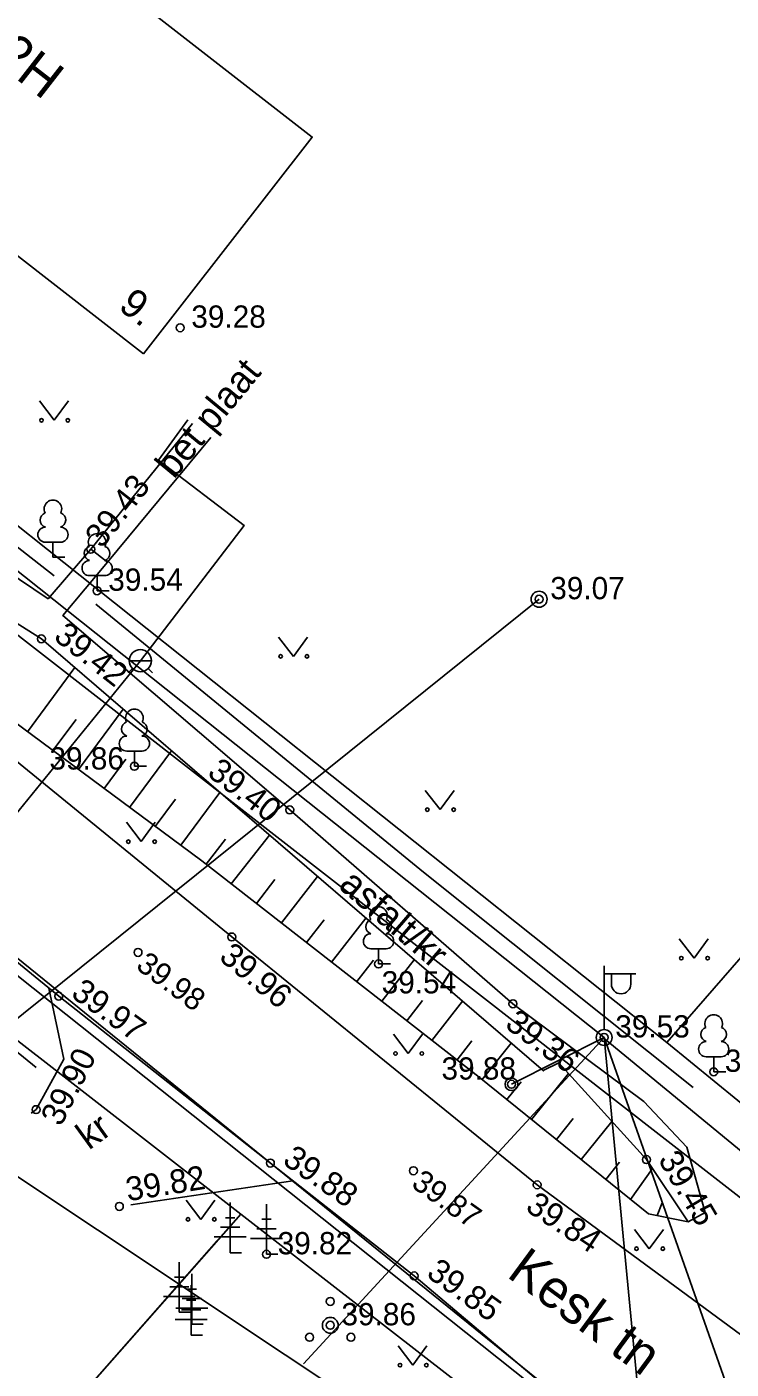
# Model space of a CAD drawing. Extents: x 641898 to 642452, y 6471715 to 6472255.
# Drawn here: x 642337.37 to 642359.52, y 6471802.88 to 6471845.1 of the extents above; entities that cross this region are included whole.
import ezdxf

# ---------------------------------------------------------------- set-up
doc = ezdxf.new("R2010")
doc.units = 0
for name, color, linetype in [('HALJASTUS', 7, 'Continuous'), ('HOONE', 7, 'Continuous'), ('KORGUS-EH2000', 7, 'Continuous'), ('KTRASS', 7, 'Continuous'), ('MPOHULIIN', 7, 'Continuous'), ('PIIR', 7, 'Continuous'), ('POST', 7, 'Continuous'), ('PUU', 7, 'Continuous'), ('RELJEEF', 7, 'Continuous'), ('SIOHULIIN', 7, 'Continuous'), ('TEE', 7, 'Continuous'), ('VKAEV', 7, 'Continuous'), ('VTRASS', 7, 'Continuous')]:
    doc.layers.add(name, color=color, linetype=linetype)

msp = doc.modelspace()

# ---------------------------------------------------------------- linework, layer by layer
at = {"layer": 'HALJASTUS'}
for p, q in [((642337.772, 6471833.33), (642338.235, 6471832.723)), ((642338.235, 6471832.723), (642338.681, 6471833.33)), ((642345.289, 6471825.904), (642345.752, 6471825.297)), ((642345.752, 6471825.297), (642346.198, 6471825.904)), ((642349.899, 6471821.085), (642350.363, 6471820.478)), ((642350.363, 6471820.478), (642350.808, 6471821.085)), ((642340.503, 6471820.079), (642340.966, 6471819.472)), ((642340.966, 6471819.472), (642341.412, 6471820.079)), ((642357.886, 6471816.413), (642358.35, 6471815.807)), ((642358.35, 6471815.807), (642358.795, 6471816.413)), ((642348.901, 6471813.416), (642349.364, 6471812.81)), ((642349.364, 6471812.81), (642349.81, 6471813.416)), ((642342.378, 6471808.199), (642342.842, 6471807.592)), ((642342.842, 6471807.592), (642343.287, 6471808.199)), ((642356.477, 6471807.276), (642356.94, 6471806.669)), ((642356.94, 6471806.669), (642357.386, 6471807.276)), ((642349.044, 6471803.615), (642349.507, 6471803.009)), ((642349.507, 6471803.009), (642349.953, 6471803.615))]:
    msp.add_line(p, q, dxfattribs=at)
for points in [[(642338.237, 6471827.832), (642333.487, 6471831.54), (642329.756, 6471834.57), (642322.893, 6471840.028), (642321.288, 6471841.543), (642315.856, 6471845.602)], [(642315.02, 6471830.765), (642322.645, 6471824.366), (642330.843, 6471817.92), (642337.665, 6471812.365)], [(642358.324, 6471811.739), (642349.848, 6471818.515), (642339.538, 6471826.94)]]:
    msp.add_lwpolyline(points, dxfattribs=at)
for centre in [(642337.834, 6471832.723), (642338.663, 6471832.723), (642345.351, 6471825.297), (642346.18, 6471825.297), (642349.962, 6471820.478), (642350.79, 6471820.478), (642340.565, 6471819.472), (642341.394, 6471819.472), (642357.949, 6471815.807), (642358.777, 6471815.807), (642348.963, 6471812.81), (642349.792, 6471812.81), (642342.441, 6471807.592), (642343.269, 6471807.592), (642356.539, 6471806.669), (642357.368, 6471806.669), (642349.106, 6471803.009), (642349.935, 6471803.009)]:
    msp.add_circle(centre, 0.055, dxfattribs=at)
at = {"layer": 'HOONE'}
msp.add_lwpolyline([(642341.045, 6471834.813), (642327.491, 6471845.358), (642330.674, 6471849.455), (642329.02, 6471850.529), (642329.906, 6471851.774), (642331.522, 6471850.559), (642332.775, 6471852.187), (642346.347, 6471841.629), (642341.045, 6471834.813)], dxfattribs=at)
at = {"layer": 'KORGUS-EH2000'}
for centre in [(642342.194, 6471835.634), (642339.384, 6471828.665), (642339.583, 6471827.362), (642353.478, 6471827.095), (642337.832, 6471825.85), (642340.755, 6471821.843), (642345.639, 6471820.471), (642343.817, 6471816.473), (642340.869, 6471815.987), (642348.43, 6471815.627), (642338.375, 6471814.612), (642352.656, 6471814.372), (642355.522, 6471813.313), (642358.966, 6471812.233), (642352.61, 6471811.841), (642337.666, 6471811.043), (642345.029, 6471809.364), (642356.853, 6471809.472), (642349.528, 6471809.121), (642353.417, 6471808.678), (642340.282, 6471807.999), (642344.908, 6471806.494), (642349.55, 6471805.814), (642346.914, 6471804.261)]:
    msp.add_circle(centre, 0.125, dxfattribs=at)
at = {"layer": 'KTRASS'}
msp.add_lwpolyline([(642365.181, 6471793.039), (642325.676, 6471825.028)], dxfattribs=at)
at = {"layer": 'MPOHULIIN'}
for points in [[(642355.522, 6471813.313), (642331.534, 6471832.393), (642302.222, 6471855.921), (642271.629, 6471880.301), (642234.793, 6471909.555), (642198.436, 6471939.015), (642169.975, 6471961.956), (642133.076, 6471995.171), (642102.99, 6472021.089), (642074.552, 6472045.947), (642044.597, 6472041.824), (642019.939, 6472060.923), (641980.015, 6472091.706), (641945.513, 6472065.466), (641932.178, 6472056.628)], [(642346.067, 6471803.048), (642355.522, 6471813.313)], [(642373.322, 6471767.398), (642363.199, 6471791.543), (642355.522, 6471813.313)], [(642357.511, 6471792.498), (642355.522, 6471813.313)], [(642373.797, 6471741.516), (642403.517, 6471768.837), (642381.866, 6471791.606), (642355.525, 6471813.278)]]:
    msp.add_lwpolyline(points, dxfattribs=at)
at = {"layer": 'PIIR'}
for p, q in [((642294.31, 6471859.27), (642377.02, 6471794.87)), ((642357.49, 6471813.15), (642303.46, 6471856.17)), ((642344.1, 6471807.76), (642288.16, 6471851.19)), ((642374.64, 6471832.89), (642357.49, 6471813.15)), ((642374.36, 6471799.41), (642357.49, 6471813.15)), ((642344.1, 6471807.76), (642326.114, 6471787.348)), ((642343.35, 6471806.91), (642344.1, 6471807.76)), ((642370.2, 6471787.49), (642344.1, 6471807.76)), ((642326.114, 6471787.348), (642343.35, 6471806.91))]:
    msp.add_line(p, q, dxfattribs=at)
at = {"layer": 'POST'}
for p, q in [((642355.522, 6471813.563), (642355.522, 6471815.563)), ((642355.522, 6471815.313), (642356.522, 6471815.313)), ((642355.749, 6471814.992), (642355.749, 6471815.313)), ((642356.361, 6471814.992), (642356.361, 6471815.313)), ((642352.61, 6471811.841), (642355.522, 6471813.313))]:
    msp.add_line(p, q, dxfattribs=at)
for centre, radius in [((642353.478, 6471827.095), 0.25), ((642355.522, 6471813.313), 0.25), ((642352.61, 6471811.841), 0.2)]:
    msp.add_circle(centre, radius, dxfattribs=at)
msp.add_arc((642356.055, 6471814.992), 0.306, 180, 0, dxfattribs=at)
at = {"layer": 'PUU'}
for p, q in [((642338.433, 6471828.889), (642337.953, 6471828.889)), ((642338.193, 6471828.414), (642338.193, 6471828.889)), ((642338.573, 6471828.414), (642338.193, 6471828.414)), ((642339.823, 6471827.837), (642339.343, 6471827.837)), ((642339.583, 6471827.362), (642339.583, 6471827.837)), ((642339.963, 6471827.362), (642339.583, 6471827.362)), ((642340.995, 6471822.318), (642340.515, 6471822.318)), ((642340.755, 6471821.843), (642340.755, 6471822.318)), ((642341.135, 6471821.843), (642340.755, 6471821.843)), ((642348.67, 6471816.102), (642348.19, 6471816.102)), ((642348.43, 6471815.627), (642348.43, 6471816.102)), ((642348.81, 6471815.627), (642348.43, 6471815.627)), ((642359.206, 6471812.708), (642358.726, 6471812.708)), ((642358.966, 6471812.233), (642358.966, 6471812.708)), ((642359.346, 6471812.233), (642358.966, 6471812.233)), ((642343.767, 6471806.544), (642343.767, 6471808.119)), ((642344.908, 6471806.494), (642344.908, 6471808.069)), ((642344.067, 6471807.344), (642343.467, 6471807.344)), ((642343.917, 6471807.644), (642343.617, 6471807.644)), ((642345.208, 6471807.294), (642344.608, 6471807.294)), ((642345.058, 6471807.594), (642344.758, 6471807.594)), ((642344.267, 6471807.044), (642343.267, 6471807.044)), ((642345.408, 6471806.994), (642344.408, 6471806.994)), ((642344.127, 6471806.544), (642343.767, 6471806.544)), ((642345.268, 6471806.494), (642344.908, 6471806.494)), ((642342.165, 6471804.67), (642342.165, 6471806.245)), ((642342.315, 6471805.77), (642342.015, 6471805.77)), ((642342.561, 6471804.3), (642342.561, 6471805.875)), ((642342.665, 6471805.17), (642341.665, 6471805.17)), ((642342.465, 6471805.47), (642341.865, 6471805.47)), ((642342.711, 6471805.4), (642342.411, 6471805.4)), ((642342.539, 6471803.948), (642342.539, 6471805.523)), ((642343.061, 6471804.8), (642342.061, 6471804.8)), ((642342.839, 6471804.748), (642342.239, 6471804.748)), ((642342.861, 6471805.1), (642342.261, 6471805.1)), ((642342.689, 6471805.048), (642342.389, 6471805.048)), ((642343.039, 6471804.448), (642342.039, 6471804.448)), ((642342.525, 6471804.67), (642342.165, 6471804.67)), ((642342.921, 6471804.3), (642342.561, 6471804.3)), ((642342.899, 6471803.948), (642342.539, 6471803.948))]:
    msp.add_line(p, q, dxfattribs=at)
for centre, radius in [((642346.914, 6471805.011), 0.125), ((642346.914, 6471804.261), 0.25), ((642346.264, 6471803.886), 0.125), ((642347.564, 6471803.886), 0.125)]:
    msp.add_circle(centre, radius, dxfattribs=at)
for centre, radius, start, end in [((642338.193, 6471829.934), 0.277, 332.5799, 207.4201), ((642338.023, 6471829.587), 0.233, 109.0217, 253.1415), ((642338.363, 6471829.587), 0.233, 286.8508, 70.9859), ((642337.956, 6471829.126), 0.238, 90.0016, 269.3953), ((642338.43, 6471829.126), 0.238, 270.6047, 89.9984), ((642339.583, 6471828.882), 0.277, 332.5799, 207.4201), ((642339.413, 6471828.535), 0.233, 109.0217, 253.1415), ((642339.753, 6471828.535), 0.233, 286.8508, 70.9859), ((642339.346, 6471828.074), 0.238, 90.0016, 269.3953), ((642339.82, 6471828.074), 0.238, 270.6047, 89.9984), ((642340.755, 6471823.363), 0.277, 332.5799, 207.4201), ((642340.585, 6471823.016), 0.233, 109.0217, 253.1415), ((642340.925, 6471823.016), 0.233, 286.8508, 70.9859), ((642340.518, 6471822.555), 0.238, 90.0016, 269.3953), ((642340.992, 6471822.555), 0.238, 270.6047, 89.9984), ((642348.43, 6471817.147), 0.277, 332.5799, 207.4201), ((642348.26, 6471816.8), 0.233, 109.0217, 253.1415), ((642348.6, 6471816.8), 0.233, 286.8508, 70.9859), ((642348.193, 6471816.339), 0.238, 90.0016, 269.3953), ((642348.667, 6471816.339), 0.238, 270.6047, 89.9984), ((642358.966, 6471813.753), 0.277, 332.5799, 207.4201), ((642358.796, 6471813.406), 0.233, 109.0217, 253.1415), ((642359.136, 6471813.406), 0.233, 286.8508, 70.9859), ((642358.729, 6471812.945), 0.238, 90.0016, 269.3953), ((642359.203, 6471812.945), 0.238, 270.6047, 89.9984)]:
    msp.add_arc(centre, radius, start, end, dxfattribs=at)
at = {"layer": 'RELJEEF'}
for p, q in [((642337.392, 6471822.929), (642338.885, 6471824.943)), ((642338.92, 6471823.312), (642338.195, 6471822.334)), ((642338.999, 6471821.739), (642340.404, 6471823.635)), ((642340.483, 6471822.062), (642339.802, 6471821.143)), ((642340.606, 6471820.548), (642341.924, 6471822.326)), ((642342.046, 6471820.812), (642341.409, 6471819.952)), ((642342.213, 6471819.357), (642343.446, 6471821.014)), ((642343.619, 6471819.551), (642343.014, 6471818.758)), ((642343.802, 6471818.143), (642344.999, 6471819.677)), ((642345.174, 6471818.276), (642344.59, 6471817.528)), ((642345.379, 6471816.913), (642346.516, 6471818.371)), ((642346.721, 6471817.008), (642346.167, 6471816.298)), ((642346.956, 6471815.683), (642348.033, 6471817.064)), ((642348.268, 6471815.739), (642347.744, 6471815.068)), ((642348.533, 6471814.453), (642349.55, 6471815.757)), ((642349.815, 6471814.471), (642349.321, 6471813.838)), ((642350.11, 6471813.222), (642351.068, 6471814.45)), ((642351.363, 6471813.202), (642350.898, 6471812.607)), ((642351.685, 6471811.991), (642352.595, 6471813.135)), ((642352.912, 6471811.919), (642352.463, 6471811.363)), ((642353.242, 6471810.735), (642354.404, 6471812.175)), ((642354.552, 6471810.766), (642354.02, 6471810.107)), ((642354.798, 6471809.479), (642355.763, 6471810.675)), ((642356.01, 6471809.388), (642355.576, 6471808.851)), ((642356.354, 6471808.222), (642357.04, 6471809.194)), ((642357.344, 6471808.11), (642357.188, 6471807.712))]:
    msp.add_line(p, q, dxfattribs=at)
msp.add_lwpolyline([(642358.168, 6471807.514), (642356.92, 6471807.766), (642351.592, 6471812.066), (642342.878, 6471818.864), (642334.715, 6471824.913), (642329.886, 6471829.377), (642321.394, 6471836.472), (642313.104, 6471842.93)], dxfattribs=at)
at = {"layer": 'SIOHULIIN'}
msp.add_lwpolyline([(642382.916, 6471799.858), (642363.199, 6471791.543), (642333.683, 6471811.198), (642353.478, 6471827.095)], dxfattribs=at)
at = {"layer": 'TEE'}
for points in [[(642366.559, 6471781.691), (642366.75, 6471785.551), (642365.695, 6471788.509), (642364.88, 6471791.554), (642359.32, 6471797.565), (642349.55, 6471805.814), (642345.029, 6471809.364), (642338.375, 6471814.612), (642330.338, 6471821.174), (642323.486, 6471826.682), (642313.328, 6471834.865), (642303.076, 6471843.066), (642293.352, 6471850.788), (642283.707, 6471858.589), (642276.578, 6471864.269), (642271.231, 6471868.612), (642264.701, 6471873.908), (642253.944, 6471882.162), (642243.566, 6471890.342)], [(642383.211, 6471751.926), (642385.791, 6471761.757), (642386.251, 6471768.397), (642385.085, 6471777.246), (642381.999, 6471784.94), (642376.754, 6471790.765), (642370.195, 6471795.981), (642371.442, 6471797.485), (642368.827, 6471798.665), (642362.827, 6471801.747), (642353.417, 6471808.678), (642343.817, 6471816.473), (642335.394, 6471823.345), (642333.841, 6471824.933), (642323.652, 6471832.89), (642313.851, 6471840.582), (642312.566, 6471842.194), (642313.903, 6471844.023), (642314.481, 6471844.192), (642315.921, 6471842.975), (642316.454, 6471843.473), (642314.647, 6471845.18)], [(642315.921, 6471842.975), (642321.043, 6471839.324), (642329.05, 6471832.354), (642336.751, 6471826.527), (642337.832, 6471825.85), (642353.612, 6471812.259), (642353.604, 6471812.269), (642354.098, 6471812.513), (642356.853, 6471809.472), (642358.168, 6471807.514), (642358.699, 6471807.804), (642358.121, 6471809.863), (642356.774, 6471811.304), (642352.656, 6471814.372), (642345.639, 6471820.471), (642338.503, 6471826.585), (642339.912, 6471828.256), (642339.384, 6471828.665), (642338.042, 6471827.11), (642333.05, 6471830.468), (642321.569, 6471839.628), (642316.454, 6471843.473)], [(642342.579, 6471832.623), (642339.384, 6471828.665)], [(642343.154, 6471832.18), (642339.912, 6471828.256)], [(642338.064, 6471814.866), (642338.539, 6471812.629), (642337.666, 6471811.043), (642337.514, 6471810.933)], [(642340.639, 6471808.052), (642345.736, 6471808.809)]]:
    msp.add_lwpolyline(points, dxfattribs=at)
at = {"layer": 'VKAEV'}
for p, q in [((642340.592, 6471825.162), (642341.292, 6471825.162)), ((642340.695, 6471824.915), (642340.555, 6471824.775)), ((642341.189, 6471824.915), (642341.329, 6471824.775))]:
    msp.add_line(p, q, dxfattribs=at)
msp.add_circle((642340.942, 6471825.162), 0.35, dxfattribs=at)
at = {"layer": 'VTRASS'}
for points in [[(642383.722, 6471805.593), (642379.745, 6471805.698), (642375.961, 6471804.651), (642372.001, 6471801.12), (642371.83, 6471800.837), (642365.292, 6471792.802), (642334.532, 6471817.276), (642325.31, 6471824.815), (642293.796, 6471849.944), (642275.212, 6471864.371), (642256.629, 6471878.798), (642256.057, 6471879.253), (642241.436, 6471890.95)], [(642334.532, 6471817.276), (642340.942, 6471825.162), (642344.21, 6471829.41), (642341.513, 6471831.471), (642342.436, 6471832.732)]]:
    msp.add_lwpolyline(points, dxfattribs=at)

# ---------------------------------------------------------------- texts
at = {"layer": 'HOONE'}
for s, height, p in [('2H', 1.2, (642336.289, 6471844.032)), ('9.', 0.9, (642340.216, 6471836.237))]:
    msp.add_text(s, height=height, rotation=322.1191, dxfattribs=at).set_placement(p)
at = {"layer": 'KORGUS-EH2000'}
for s, p in [('39.28', (642342.544, 6471835.634)), ('39.54', (642339.933, 6471827.362)), ('39.07', (642353.828, 6471827.095)), ('39.86', (642338.084, 6471821.739)), ('39.54', (642348.528, 6471814.698)), ('39.53', (642355.872, 6471813.313)), ('39.51', (642359.316, 6471812.233)), ('39.88', (642350.41, 6471811.988)), ('39.82', (642345.258, 6471806.494)), ('39.86', (642347.264, 6471804.261))]:
    msp.add_text(s, height=0.7, dxfattribs=at).set_placement(p)
for s, height, rotation, p in [('39.43', 0.75, 51.7924, (642339.734, 6471828.665)), ('39.42', 0.75, 321.8458, (642338.182, 6471825.85)), ('39.40', 0.75, 322.2674, (642343.012, 6471821.567)), ('39.96', 0.75, 320.2976, (642343.381, 6471815.782)), ('39.98', 0.7, 323.3622, (642340.768, 6471815.498)), ('39.97', 0.75, 324.2136, (642338.725, 6471814.612)), ('39.36', 0.75, 323.4311, (642352.368, 6471813.65)), ('39.90', 0.75, 63.1177, (642338.444, 6471810.484)), ('39.88', 0.75, 325.2887, (642345.377, 6471809.362)), ('39.45', 0.75, 300.5809, (642357.203, 6471809.472)), ('39.82', 0.75, 9.0448, (642340.546, 6471808.162)), ('39.87', 0.7, 324.6035, (642349.425, 6471808.634)), ('39.84', 0.75, 326.4335, (642353.012, 6471807.889)), ('39.85', 0.75, 324.1015, (642349.9, 6471805.814))]:
    msp.add_text(s, height=height, rotation=rotation, dxfattribs=at).set_placement(p)
at = {"layer": 'TEE'}
for s, height, rotation, p in [('bet plaat', 0.85, 50.4387, (642342, 6471830.85)), ('asfalt/kr', 0.85, 319.2623, (642347.137, 6471818.038)), ('kr', 0.85, 35.9117, (642339.323, 6471809.754)), ('Kesk tn', 1.2, 323.6262, (642352.426, 6471805.808))]:
    msp.add_text(s, height=height, rotation=rotation, dxfattribs=at).set_placement(p)

doc.saveas('drawing.dxf')
